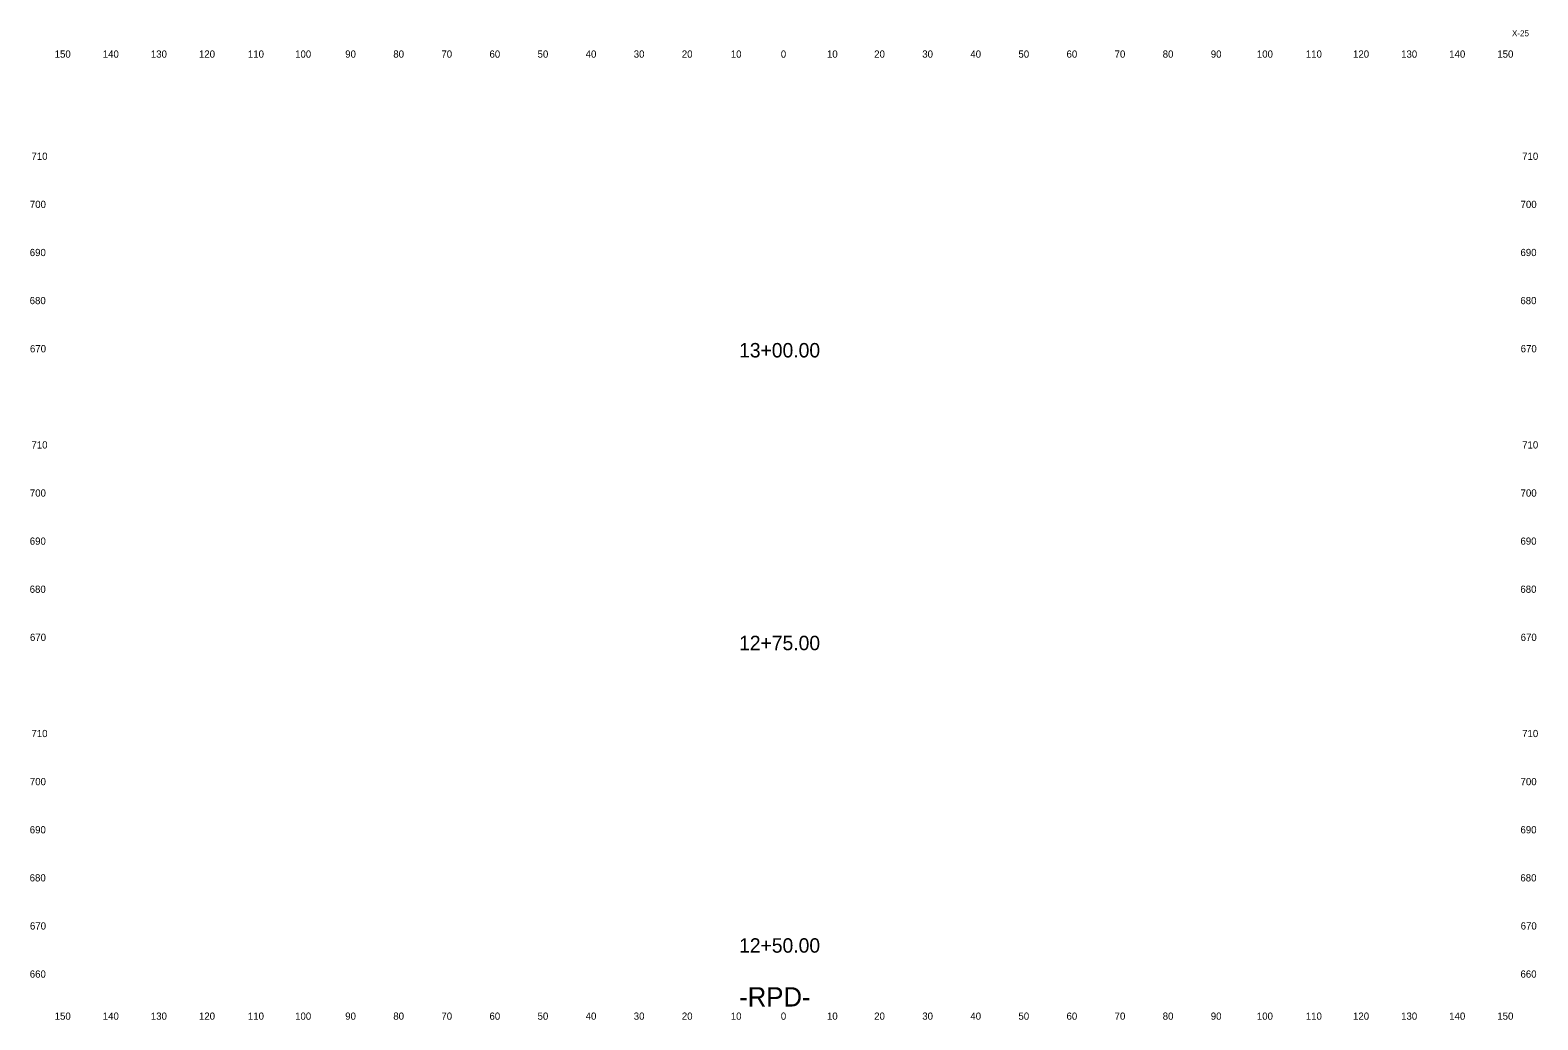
# Model space of a CAD drawing. Extents: x 3 to 317, y 1 to 867.
# Drawn here: x 3.3 to 316.9, y 441.2 to 647 of the extents above; entities that cross this region are included whole.
import ezdxf

# ---------------------------------------------------------------- set-up
doc = ezdxf.new("R2010")
doc.units = 0
for name, color, linetype in [('Prop XS Alignment Label', 7, 'Continuous'), ('Prop XS Elevation Labels', 7, 'Continuous'), ('Prop XS Offset Labels', 7, 'Continuous'), ('Prop XS Sheet Number', 7, 'Continuous'), ('Prop XS Station Labels', 7, 'Continuous')]:
    doc.layers.add(name, color=color, linetype=linetype)

msp = doc.modelspace()

# ---------------------------------------------------------------- texts
at = {"layer": 'Prop XS Alignment Label'}
msp.add_text('-RPD-', height=4, dxfattribs=at).set_placement((150.78, 444))
at = {"layer": 'Prop XS Elevation Labels'}
for s, p in [('710', (3.61, 620)), ('710', (313.61, 620)), ('700', (3.28, 610)), ('700', (313.28, 610)), ('690', (3.26, 600)), ('690', (313.26, 600)), ('680', (3.24, 590)), ('680', (313.24, 590)), ('670', (3.3, 580)), ('670', (313.3, 580)), ('710', (3.61, 560)), ('710', (313.61, 560)), ('700', (3.28, 550)), ('700', (313.28, 550)), ('690', (3.26, 540)), ('690', (313.26, 540)), ('680', (3.24, 530)), ('680', (313.24, 530)), ('670', (3.3, 520)), ('670', (313.3, 520)), ('710', (3.61, 500)), ('710', (313.61, 500)), ('700', (3.28, 490)), ('700', (313.28, 490)), ('690', (3.26, 480)), ('690', (313.26, 480)), ('680', (3.24, 470)), ('680', (313.24, 470)), ('670', (3.3, 460)), ('670', (313.3, 460)), ('660', (3.26, 450)), ('660', (313.26, 450))]:
    msp.add_text(s, height=1.5, dxfattribs=at).set_placement(p)
at = {"layer": 'Prop XS Offset Labels'}
for s, p in [('150', (8.44, 641.25)), ('140', (18.44, 641.25)), ('130', (28.44, 641.25)), ('120', (38.44, 641.25)), ('110', (48.62, 641.25)), ('100', (58.44, 641.25)), ('90', (68.86, 641.25)), ('80', (78.86, 641.25)), ('70', (88.86, 641.25)), ('60', (98.86, 641.25)), ('50', (108.86, 641.25)), ('40', (118.86, 641.25)), ('30', (128.86, 641.25)), ('20', (138.86, 641.25)), ('10', (149.04, 641.25)), ('0', (159.45, 641.25)), ('10', (169.04, 641.25)), ('20', (178.86, 641.25)), ('30', (188.86, 641.25)), ('40', (198.86, 641.25)), ('50', (208.86, 641.25)), ('60', (218.86, 641.25)), ('70', (228.86, 641.25)), ('80', (238.86, 641.25)), ('90', (248.86, 641.25)), ('100', (258.44, 641.25)), ('110', (268.62, 641.25)), ('120', (278.44, 641.25)), ('130', (288.44, 641.25)), ('140', (298.44, 641.25)), ('150', (308.44, 641.25)), ('150', (8.44, 441.25)), ('140', (18.44, 441.25)), ('130', (28.44, 441.25)), ('120', (38.44, 441.25)), ('110', (48.62, 441.25)), ('100', (58.44, 441.25)), ('90', (68.86, 441.25)), ('80', (78.86, 441.25)), ('70', (88.86, 441.25)), ('60', (98.86, 441.25)), ('50', (108.86, 441.25)), ('40', (118.86, 441.25)), ('30', (128.86, 441.25)), ('20', (138.86, 441.25)), ('10', (149.04, 441.25)), ('0', (159.45, 441.25)), ('10', (169.04, 441.25)), ('20', (178.86, 441.25)), ('30', (188.86, 441.25)), ('40', (198.86, 441.25)), ('50', (208.86, 441.25)), ('60', (218.86, 441.25)), ('70', (228.86, 441.25)), ('80', (238.86, 441.25)), ('90', (248.86, 441.25)), ('100', (258.44, 441.25)), ('110', (268.62, 441.25)), ('120', (278.44, 441.25)), ('130', (288.44, 441.25)), ('140', (298.44, 441.25)), ('150', (308.44, 441.25))]:
    msp.add_text(s, height=1.5, dxfattribs=at).set_placement(p)
at = {"layer": 'Prop XS Sheet Number'}
msp.add_text('X-25', height=1.25, dxfattribs=at).set_placement((311.5, 645.7))
at = {"layer": 'Prop XS Station Labels'}
for s, p in [('13+00.00', (150.77, 578.93)), ('12+75.00', (150.77, 518.07)), ('12+50.00', (150.77, 455.19))]:
    msp.add_text(s, height=3, dxfattribs=at).set_placement(p)

doc.saveas('drawing.dxf')
